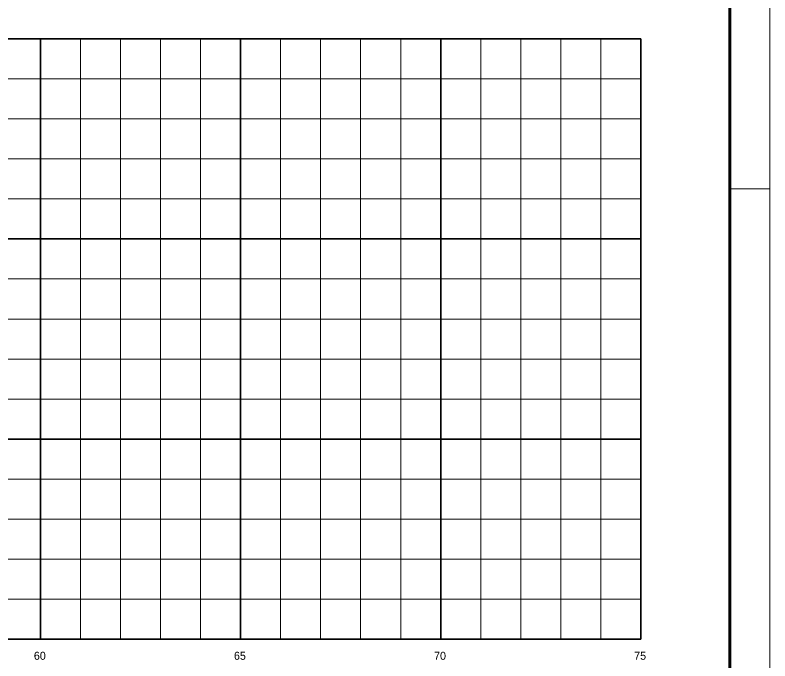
# Model space of a CAD drawing. Extents: x 949 to 2631, y -1701 to -513.
# Drawn here: x 2253.7 to 2630.9, y -1342.6 to -1019.9 of the extents above; entities that cross this region are included whole.
import ezdxf
from ezdxf.enums import TextEntityAlignment as Align

# ---------------------------------------------------------------- set-up
doc = ezdxf.new("R2010")
doc.units = 0
doc.header["$LTSCALE"] = 1.2
for name, color, linetype, lineweight in [('1', 7, 'Continuous', 13), ('2', 7, 'Continuous', 13), ('35', 7, 'Continuous', 35), ('5', 7, 'Continuous', 13), ('6', 7, 'Continuous', 60), ('7', 7, 'Continuous', 35)]:
    doc.layers.add(name, color=color, linetype=linetype, lineweight=lineweight)

msp = doc.modelspace()

# ---------------------------------------------------------------- linework, layer by layer
at = {"layer": '2'}
msp.add_line((2630.926, -512.728), (2630.926, -1700.728), dxfattribs=at)
at = {"layer": '35'}
msp.add_line((1066.405, -1231.771), (2466.405, -1231.771), dxfattribs=at)
at = {"layer": '5'}
for p, q in [((2546.405, -1031.771), (2546.405, -1331.771)), ((2566.405, -1031.771), (2566.405, -1331.771)), ((1066.405, -1051.771), (2566.405, -1051.771)), ((1066.405, -1071.771), (2566.405, -1071.771)), ((1066.405, -1091.771), (2566.405, -1091.771)), ((2610.926, -1106.728), (2630.926, -1106.728)), ((1066.405, -1111.771), (2566.405, -1111.771)), ((1066.405, -1151.771), (2566.405, -1151.771)), ((1066.405, -1171.771), (2566.405, -1171.771)), ((1066.405, -1191.771), (2566.405, -1191.771)), ((1066.405, -1211.771), (2566.405, -1211.771)), ((1066.405, -1251.771), (2566.405, -1251.771)), ((1066.405, -1271.771), (2566.405, -1271.771)), ((1066.405, -1291.771), (2566.405, -1291.771)), ((1066.405, -1311.771), (2566.405, -1311.771))]:
    msp.add_line(p, q, dxfattribs=at)
at = {"layer": '6'}
msp.add_line((2610.926, -532.728), (2610.926, -1680.728), dxfattribs=at)
at = {"layer": '7'}
for p, q in [((1066.405, -1031.771), (2566.405, -1031.771)), ((2266.405, -1031.771), (2266.405, -1331.771)), ((2366.405, -1031.771), (2366.405, -1331.771)), ((2466.405, -1031.771), (2466.405, -1331.771)), ((2566.405, -1031.771), (2566.405, -1331.771)), ((2566.405, -1031.771), (2566.405, -1331.771)), ((1066.405, -1131.771), (2566.405, -1131.771)), ((1066.405, -1231.771), (2566.405, -1231.771)), ((2566.405, -1331.771), (1007.352, -1331.771))]:
    msp.add_line(p, q, dxfattribs=at)
at = {"layer": '7', "lineweight": 13}
for p, q in [((2286.405, -1031.771), (2286.405, -1331.771)), ((2306.405, -1031.771), (2306.405, -1331.771)), ((2326.405, -1031.771), (2326.405, -1331.771)), ((2346.405, -1031.771), (2346.405, -1331.771)), ((2386.405, -1031.771), (2386.405, -1331.771)), ((2406.405, -1031.771), (2406.405, -1331.771)), ((2426.405, -1031.771), (2426.405, -1331.771)), ((2446.405, -1031.771), (2446.405, -1331.771)), ((2486.405, -1031.771), (2486.405, -1331.771)), ((2506.405, -1031.771), (2506.405, -1331.771)), ((2526.405, -1031.771), (2526.405, -1331.771)), ((2546.405, -1031.771), (2546.405, -1331.771))]:
    msp.add_line(p, q, dxfattribs=at)

# ---------------------------------------------------------------- texts
at = {"layer": '1'}
for s, p in [('60', (2266.076, -1342.071)), ('65', (2366.076, -1342.071)), ('70', (2466.076, -1342.071)), ('75', (2566.076, -1342.071))]:
    msp.add_text(s, height=4, dxfattribs=at).set_placement(p, align=Align.CENTER)

doc.saveas('drawing.dxf')
